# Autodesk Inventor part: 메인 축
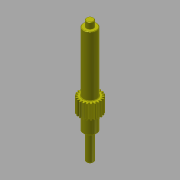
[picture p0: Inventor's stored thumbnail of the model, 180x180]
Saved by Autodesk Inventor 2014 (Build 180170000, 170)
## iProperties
Created: 2016-02
Part Number: 메인 축
Material: 강철, 연강
Document SubType Name: Modeling
Categories: <?xml version="1.0" encoding="UTF-16"?> <MemberInstance><Categories><FamilyTemplate><FamilyTemplateParameter ValueType="xs:double" Id="1" ObjectReferenceKey="da
Density: 7.86 g/cm^3
Mass: 181.397 g
Surface Area: 79.0018 cm^2
Volume: 23.0784 cm^3
Appearance: 노란색
Author: mdu
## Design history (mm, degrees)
sketch "Sketch1"
  geometry: C1 r 12 at (0, 0)
  constraints: 1 centre point
  dimensions: "d0" = 24 diameter of C1 (= da_da)
extrude "Extrusion1" new body sketch "Sketch1" distance "d1" = 20 (= da_b); taper "d2" = 0 deg
workplane "Work Plane2"
feature "피치 지름" dims "d4" = 10, "d5" = 0
workplane "Work Plane8"
workplane "Work Plane9"
chamfer "모따기1" distance "d49" = 1; stored, may be unused: second distance "d50" = 2, angle "d51" = 45 deg
sketch "스케치3"
  geometry: C1 r 7.5 at (0, 0); 1 further point
  constraints: 1 centre point, 1 coincident
  dimensions: "d52" = 15 diameter of C1
extrude "돌출2" join sketch "스케치3" distance "d53" = 66; taper "d54" = 0 deg
sketch "스케치4"
  geometry: C1 r 4 at (0, 0); 1 further point
  constraints: 1 centre point, 1 coincident
  dimensions: "d55" = 8 diameter of C1
extrude "돌출3" join sketch "스케치4" distance "d56" = 7; taper "d57" = 0 deg
sketch "스케치5"
  geometry: C1 r 7.5 at (0, 0) reference; C2 r 7.5 at (0, 0) reference; 1 further point
extrude "돌출4" join sketch "스케치5" distance "d62" = 16; taper "d63" = 0 deg
sketch "스케치6"
  geometry: C1 r 4 at (0, 0); 1 further point
  constraints: 1 centre point, 1 coincident
  dimensions: "d64" = 8 diameter of C1
extrude "돌출5" join sketch "스케치6" distance "d65" = 30; taper "d66" = 0 deg
chamfer "모따기2" distance "d58" = 0.5; stored, may be unused: second distance "d59" = 2, angle "d60" = 45 deg
fillet "모깎기1" dims "d61" = 0.5
feature "스퍼 기어" dims "da_b" = 20, "da_d" = 22, "da_aw" = 31, "da_da" = 24, "da_df" = 19.5, "da_dw" = 22, angle "da_beta" = 0 deg, "da_lefttooth" = 0, "da_righttooth" = 0
sketch "스케치7" dims "d68" = 18
  geometry: C1 r 0.25 at (0, -9); 2 further points
  constraints: 2 vertical alignment, 1 centre point, 1 coincident, 2 other
  dimensions: "d67" = 0.5 diameter of C1
extrude "돌출6" join sketch "스케치7" distance "d69" = 0.3; taper "d70" = 0 deg
feature "면 이동1"
feature "면 이동2"
feature "면 이동3"
body "Solid1"
sketch "Sketch2"
  geometry: C1 r 12 at (0, 0) reference; C2 r 11 at (0, 0)
  constraints: 1 centre point, 1 coincident
  dimensions: "d3" = 22 diameter of C2 (= da_dw)
body "Srf1"
node "투영된 루프1"
other parameters: "d16" = 31 (= da_aw), "d17" = 0, "d34" = 1.428 (computed from da_z), "d39" = 0, "d41" = 0, "d43" = 31 (= da_aw), "d46" = 31 (= da_aw), "d47" = 0, "d48" = 0
